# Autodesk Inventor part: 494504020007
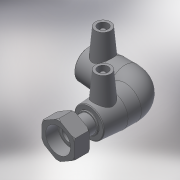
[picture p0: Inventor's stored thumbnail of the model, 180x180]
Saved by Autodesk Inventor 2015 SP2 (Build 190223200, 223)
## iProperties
Created: 2017-06
Part Number: 494504020007
Material: Generic
Description: PLASSON 90° ELBOW FEMALE FREE NUT TRANSITION 20-3/4"
Document SubType Name: Modeling
Designer: KIM
Mass: 55.0731 g
Surface Area: 148.067 cm^2
Volume: 55.0731 cm^3
Density: 1 g/cm^3
Appearance: Default
Author: KIM
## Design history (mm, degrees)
derived "494504.ipt"
feature "Solid1::494504.ipt"
tag "TaggingFeature1"
body "Solid1"
other parameters: "d2" = 32, "d4" = 22, "d5" = 28.8, "d8" = 168 deg, "d10" = 14, "d11" = 4.66667, "d29" = 38, "d30" = 15, "d31" = 36.3, "d34" = 5 deg, "d41" = 4, "d42" = 14, "d43" = 0, "d50" = 17, "d51" = 14, "d52" = 35, "d54" = 90 deg, "d58" = 35, "d59" = 0, "d61" = 90 deg, "d86" = 3, "d87" = 0, "d97" = 14, "d99" = 36.1755, "d109" = 0.6, "d116" = 15, "d117" = 24.117, "d118" = 12, "d119" = 1.2, "d120" = 19.2936, "d121" = 1.2, "d122" = 16.8819, "d123" = 14, "d124" = 1.20585, "d128" = 0, "L_" = 96, "L_1" = 35, "D_" = 14, "A_" = 38, "d_2" = 12, "D_1" = 32, "G_" = 24.117
